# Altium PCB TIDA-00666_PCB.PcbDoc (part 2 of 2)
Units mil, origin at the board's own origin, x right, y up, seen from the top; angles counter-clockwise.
Board outline 1800 x 1650 mil, 4 copper layers (Layer 1 - Top Layer, Layer 2 - GND, Layer 3 - POWER, Layer 4 - Bottom Layer), stack 61.4 mil thick; 112 components, 67 nets, 298 pads, 149 vias.
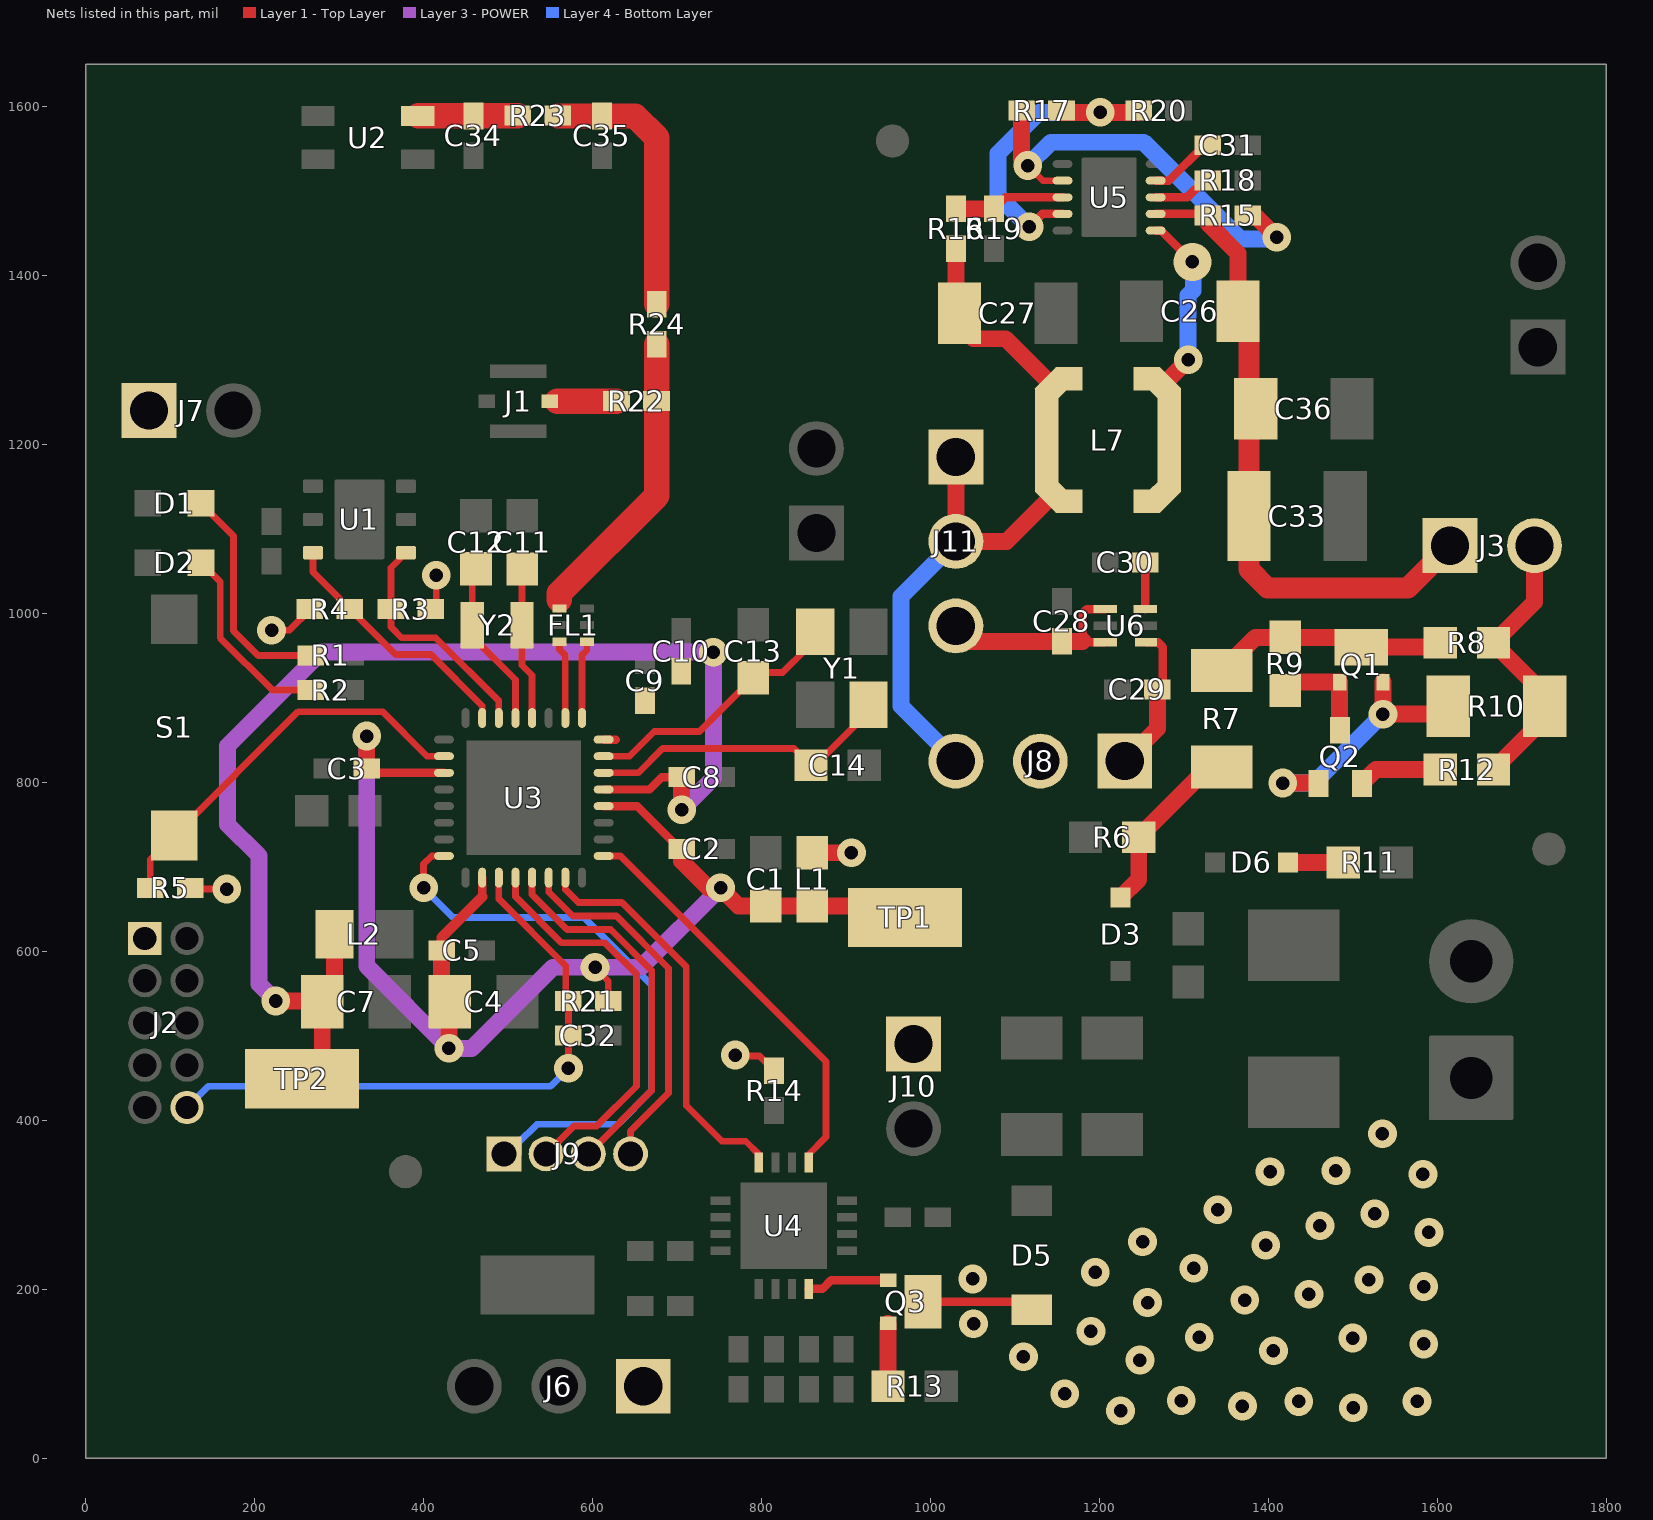
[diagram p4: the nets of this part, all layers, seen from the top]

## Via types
v1: diameter 34, hole 16, Layer 1 - Top Layer to Layer 4 - Bottom Layer, tented top, 127 vias
v2: diameter 19.68, hole 7.87, Layer 1 - Top Layer to Layer 4 - Bottom Layer, 20 vias
v3: diameter 45, hole 16, Layer 1 - Top Layer to Layer 4 - Bottom Layer, 2 vias

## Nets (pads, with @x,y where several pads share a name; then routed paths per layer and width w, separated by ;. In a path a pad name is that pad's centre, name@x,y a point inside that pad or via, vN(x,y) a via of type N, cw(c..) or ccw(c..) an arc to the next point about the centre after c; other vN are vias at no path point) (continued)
NetC30_1: C30.1 U6.3 | length 55.3
  Layer 1 - Top Layer w10: U6.3@1254.21,1005 C30.1@1254.21,1060.32
NetC31_1: C31.1 U5.4 | length 79.2
  Layer 1 - Top Layer w10: U5.4@1266.58,1512.09 1282.26,1512.09 1324.18,1554 C31.1@1328.38,1554
NetC34_1: C34.1 R23.2 U2.1 | length 117.9
  Layer 1 - Top Layer w30: U2.1@393.46,1589 R23.2@511.38,1589
NetC35_1: C35.1 R23.1 R24.1 | length 325
  Layer 1 - Top Layer w30: R23.1@559,1588.62 C35.1@611,1588.62 650.38,1588.62 676,1563 R24.1@676,1365.62
NetD1_2: D1.2 R1.1 | length 270.2
  Layer 1 - Top Layer w8: D1.2@136.5,1130 175,1091.5 175,979.17 204.17,950 R1.1@266.38,950
NetD2_2: D2.2 R2.2 | length 231.4
  Layer 1 - Top Layer w8: D2.2@136.5,1060 159.13,1037.37 159.13,970.87 221,909 R2.2@266.38,909
NetD3_1: D3.1 R6.1 R7.1 | length 213.4
  Layer 1 - Top Layer w20: D3.1@1225,663.31 1246.5,684.8 R6.1@1246.5,735 1329.41,817.91 R7.1@1345,817.91
NetD5_2: D5.2 Q3.3 | length 132.7
  Layer 1 - Top Layer w10: Q3.3@991.18,185 1110.53,185 D5.2@1120,175.53
  other v1: 1225,56 1500.33,59.63 1369.25,61.57 1436,67 1576,67 1297,68 1159,76 1248,116 1110,120 1406,127 1584,135 1500,142 1318,143 1190,150 1051,159 1257,184 1372,187 1448,194 1584,203 1519,211 1050,212 1195,220 1311.68,224.68 1397,252 1251,256 1590,267 1461,275 1526,289 1340,294 1583,336 1402,339 1480,340 1535,384
NetD6_2: D6.2 R11.2 | length 65.2
  Layer 1 - Top Layer w20: D6.2@1423.31,705 R11.2@1488.5,705
NetFL1_1: FL1.1 R22.1 R24.2 | length 349.4
  Layer 1 - Top Layer w30: 560.76,1016 560.76,1023.76 676,1139 R22.1@676,1250.62 ; R22.1@676,1251.38 R24.2@676,1318.38
NetJ1_1: J1.1 R22.2 | length 70.2
  Layer 1 - Top Layer w30: J1.1@558.13,1251 R22.2@628.38,1251
NetJ3_2: J3.2 R8.2 R10.1 R12.1 | length 335.3
  Layer 1 - Top Layer w20: R12.1@1666.5,815 1727.09,875.59 R10.1@1727.09,890 1727.09,904.41 R8.2@1666.5,965 1715,1013.5 J3.2@1715,1080
NetJ9_1: J9.1 U3.16 | length 712.7
  Layer 1 - Top Layer w8: v1(400,675) 400,703.05 409.59,712.64 U3.16@424.09,712.64
  Layer 4 - Bottom Layer w8: v1(400,675) 435,640 590,640 670,560 670,435 630,395 533.98,395 512.46,373.48 512.46,360 J9.1@495,360
NetJ9_2: J9.2 U3.20 | length 476.7
  Layer 1 - Top Layer w8: U3.20@508.74,687.05 508.74,664.54 563.41,609.87 614.96,609.87 652,572.83 652,440.07 604.88,392.95 577.95,392.95 J9.2@545,360
NetJ9_3: J9.3 U3.21 | length 447
  Layer 1 - Top Layer w8: U3.21@528.42,687.05 528.42,667.31 569.98,625.75 621.54,625.75 670,577.28 670,435 J9.3@595,360
NetJ9_4: J9.4 U3.22 | length 434.7
  Layer 1 - Top Layer w8: U3.22@548.11,687.05 548.11,670.07 576.56,641.62 628.11,641.62 690,579.73 690,431.93 645,386.93 J9.4@645,360
NetL7_1: L7.1 U5.1 | length 227.5
  Layer 1 - Top Layer w10: U5.1@1266.58,1453.03 1272.97,1453.03 v3(1310,1416) v3@1310,1410
  Layer 1 - Top Layer w20: L7.1@1274,1269 v1(1305,1300)
  Layer 4 - Bottom Layer w20: v1(1305,1300) 1305,1376 1311,1382 1311,1415 v3(1310,1416)
NetQ1_1: Q1.1 Q2.3 R9.1 | length 125.8
  Layer 1 - Top Layer w20: R9.1@1420,908.5 1430,918.5 Q1.1@1484.41,918.5 1484.41,862.09 Q2.3@1485,861.5
NetQ1_2: Q1.2 Q2.1 R10.2 | length 314.1
  Layer 1 - Top Layer w20: v1(1417,799) 1458.91,799 Q2.1@1459.41,798.5 ; Q1.2@1535.59,918.5 v1(1535.59,880.59) 1603.5,880.59 R10.2@1612.91,890
  Layer 4 - Bottom Layer w20: v1(1417,799) 1454,799 v1(1535.59,880.59)
NetQ1_3: Q1.3 R7.2 R8.1 R9.2 | length 281.8
  Layer 1 - Top Layer w20: R7.2@1345,932.09 1384.41,971.5 R9.2@1420,971.5 1498.35,971.5 Q1.3@1510,959.84 1598.35,959.84 R8.1@1603.5,965
NetQ2_2: Q2.2 R12.2 | length 99.7
  Layer 1 - Top Layer w20: Q2.2@1510.59,798.5 1527.09,815 R12.2@1603.5,815
NetQ3_1: Q3.1 U4.16 | length 98.3
  Layer 1 - Top Layer w10: U4.16@855.87,200.2 872.2,200.2 882.59,210.59 Q3.1@949.84,210.59
NetQ3_2: Q3.2 R13.2 | length 74.4
  Layer 1 - Top Layer w20: R13.2@949.84,85 Q3.2@949.84,159.41
NetR15_1: R15.1 R17.2 U5.7 | length 513.7
  Layer 1 - Top Layer w8: v1(1115,1530) 1132.91,1512.09 U5.7@1156.35,1512.09
  Layer 1 - Top Layer w20: R17.2@1107.84,1595 1107.84,1537.16 v1(1115,1530) ; R15.1@1375.62,1471 1384,1471 v1(1410,1445)
  Layer 4 - Bottom Layer w20: v1(1115,1530) 1142.52,1557.52 1252.48,1557.52 1367,1443 v1@1408,1443
NetR16_1: R16.1 R19.2 U5.8 | length 132.1
  Layer 1 - Top Layer w10: R19.2@1075,1478.62 1088.78,1492.4 U5.8@1156.35,1492.4
  Layer 1 - Top Layer w20: R16.1@1030,1478.62 R19.2@1075,1478.62
NetR17_1: R17.1 R20.2 U5.9 | length 386
  Layer 1 - Top Layer w10: v1(1116.96,1457.4) 1132.28,1472.72 U5.9@1156.35,1472.72
  Layer 1 - Top Layer w20: R17.1@1155.09,1595 1153.09,1593 v1(1201,1593) 1244.38,1593 R20.2@1246.38,1595
  Layer 4 - Bottom Layer w20: v1(1116.96,1457.4) 1080.13,1494.24 1080.13,1544.45 1128.68,1593 v1(1201,1593)
NetR18_2: R18.2 U5.3 | length 70
  Layer 1 - Top Layer w10: U5.3@1266.58,1492.4 1304.01,1492.4 1324.01,1512.4 R18.2@1328.34,1512.4
NRESET: C32.1 J2.10 R21.1 U3.19 | length 730.4
  Layer 1 - Top Layer w8: U3.19@489.05,687.05 489.05,661.78 568.13,582.71 568.13,543.25 571.38,540 C32.1@571.38,500 v1(571.38,461.38)
  Layer 4 - Bottom Layer w8: J2.10@120,415 145,440 550,440 v1(571.38,461.38)
RF_N: FL1.3 U3.2 | length 93.2
  Layer 1 - Top Layer w8: FL1.3@560.76,966.34 560.76,957.24 567.8,950.2 U3.2@567.8,876.02
RF_P: FL1.4 U3.1 | length 93.8
  Layer 1 - Top Layer w8: U3.1@587.48,876.02 587.48,950.48 593.24,956.24 FL1.4@593.24,966.34 ; FL1.4@594.24,966.34 FL1.4@595,965.58
SCL: R4.1 U1.6 U3.7 | length 303.4
  Layer 1 - Top Layer w8: U1.6@268.94,1071.65 268.94,1048.69 R4.1@312.62,1005 366.6,951.02 408.78,951.02 469.37,890.43 U3.7@469.37,876.02
SDA: R3.1 U1.1 U3.6 | length 279.4
  Layer 1 - Top Layer w8: U1.1@379.17,1071.65 361.38,1053.86 R3.1@361.38,1005 361.38,983.62 373.98,971.02 414.06,971.02 489.05,896.02 U3.6@489.05,876.02
SIMO: U3.25 U4.5 | length 492
  Layer 1 - Top Layer w8: U3.25@613.07,712.64 632.92,712.64 876.34,469.22 876.34,380 855.87,359.53 U4.5@855.87,349.8
SOMI: U3.23 U4.8 | length 478.9
  Layer 1 - Top Layer w8: U3.23@567.8,687.05 567.8,672.84 583.13,657.5 634.69,657.5 711,581.18 711,417 753,375 781.34,375 796.81,359.53 U4.8@796.81,349.8
USR_BTN: R5.1 S1.1 U3.10 | length 475.5
  Layer 1 - Top Layer w8: R5.1@76.38,675 76.38,708.43 S1.1@105,737.05 251.47,883.52 351.28,883.52 404.05,830.75 U3.10@424.09,830.75
VCC_SENSOR: J2.1 J6.1 J7.1 J8.2 J10.1 L1.2 R3.2 R4.2 R5.2 R14.1 | length 251.5
  Layer 1 - Top Layer w8: R5.2@123.62,675 124.62,676 127.11,673.51 v1(167,673.51) ; v1(220,980) 241.38,980 265.38,1004 R4.2@265.38,1005 ; R3.2@408.62,1005 415,1011.38 v1(415,1045) ; v1@761,476 797.62,476 R14.1@815,458.62
  Layer 1 - Top Layer w20: L1.2@860,716.5 v1(906.5,716.5)
  other v1: 769,477
VDDR: C7.1 C8.1 C9.1 C10.1 L2.2 TP2.1 U3.29 U3.32 | length 1542.2
  Layer 1 - Top Layer w10: U3.29@613.07,791.38 667.38,791.38 682.02,806.02 C8.1@705.43,806.02 ; U3.32@613.07,850.43 627.43,850.43
  Layer 1 - Top Layer w20: v1(225,541) C7.1@280,541 ; TP2.1@255.93,449.02 280,473.09 C7.1@280,540 294.57,554.57 L2.2@294.57,620 ; v1(705.43,767.4) C8.1@705.43,806.02
  Layer 3 - POWER w20: v1(225,541) 205,561 205,713 168,750 168,843 279,954 v1(743,954) 743,804.96 v1(705.43,767.4)
VDDS: C1.1 C2.1 C3.1 C4.1 C5.1 L1.1 R21.2 TP1.1 U3.11 U3.18 U3.28 | length 1635.1
  Layer 1 - Top Layer w8: v1(603,581) 603,580 618.62,564.38 R21.2@618.62,541 R21.2@618.62,540
  Layer 1 - Top Layer w10: C3.1@332.68,816.02 337.64,811.06 U3.11@424.09,811.06 ; 469.37,664.37 U3.18@469.37,687.05 ; U3.28@613.07,771.69 652.71,771.69 703.38,721.02 C2.1@705.43,721.02
  Layer 1 - Top Layer w12: C5.1@421.38,601 421.38,616.38 469.37,664.37
  Layer 1 - Top Layer w20: C3.1@332.68,816.02 v1(332.68,854.65) ; C5.1@421.38,601 421.38,548.62 430,540 v1(430,485) ; C2.1@705.43,721.02 705.43,706.57 737,675 v1(751.46,675) 772.95,653.5 C1.1@805,653.5 L1.1@860,653.5 956.5,653.5 TP1.1@970,640
  Layer 3 - POWER w20: v1(332.68,854.65) 332.68,582.32 v1(430,485) 457,485 553,581 v1(603,581) 657.46,581 v1(751.46,675)
VIN_DCDC: C26.1 C33.1 C36.1 J3.1 R15.2 U5.2 | length 769.5
  Layer 1 - Top Layer w10: U5.2@1266.58,1472.72 1326.66,1472.72 R15.2@1328.38,1471
  Layer 1 - Top Layer w20: R15.2@1328.38,1471 1328.38,1461.62 1364.05,1425.95 C26.1@1364.05,1357.4
  Layer 1 - Top Layer w25: C26.1@1364.05,1357.4 1376.91,1344.54 1376.91,1247 C33.1@1376.91,1115 1376.91,1052.09 1399,1030 1565,1030 J3.1@1615,1080
VIN_LDO: C28.1 J11.3 U6.4 U6.6 | length 243
  Layer 1 - Top Layer w10: U6.6@1206.97,965.63 1181.81,965.63 1180.31,967.13 1180.31,1000.35 1184.96,1005 U6.4@1206.97,1005
  Layer 1 - Top Layer w20: J11.3@1030,975 1038.31,966.69 C28.1@1155.59,966.69 1179.88,966.69 1180.31,967.13
VOUT_DCDC: C27.1 J8.3 J11.1 J11.2 L7.2 R16.2 | length 786.2
  Layer 1 - Top Layer w20: J11.1@1030,1185 J11.2@1030,1085 1090,1085 L7.2@1146,1141 ; R16.2@1030,1431.38 1030,1359.38 C27.1@1034.38,1355 1034.38,1341.33 1050.71,1325 1089,1325 L7.2@1145.5,1268.5
  Layer 4 - Bottom Layer w20: J8.3@1030,825 965,890 965,1020 J11.2@1030,1085
VOUT_LDO: C29.1 J8.1 U6.1 | length 176
  Layer 1 - Top Layer w10: U6.1@1255,965.63 1269.37,965.63 1275,960 1275,916.38 C29.1@1268.62,910
  Layer 1 - Top Layer w20: J8.1@1230,825 1268.62,863.62 C29.1@1268.62,910
X24M_N: C14.1 U3.30 Y1.1 | length 352.9
  Layer 1 - Top Layer w8: U3.30@613.07,811.06 654.09,811.06 683.03,840 838.5,840 C14.1@858.5,820 ; C14.1@861,817.5 916.5,872.99 Y1.1@916.5,881.69
X24M_P: C13.1 U3.31 Y1.3 | length 303.2
  Layer 1 - Top Layer w8: U3.31@613.07,830.75 643.78,830.75 673.03,860 726.5,860 C13.1@790,923.5 796.5,930 825,930 853.5,958.5 Y1.3@853.5,968.31
X32K_Q1: C11.2 U3.4 Y2.1 | length 181.6
  Layer 1 - Top Layer w8: C11.2@517,1052.5 516.53,1052.03 Y2.1@516.53,986 516.53,938.47 528.42,926.57 U3.4@528.42,876.02
X32K_Q2: C12.1 U3.5 Y2.2 | length 184.8
  Layer 1 - Top Layer w8: Y2.2@457.47,986 457.47,1047.94 C12.1@462.06,1052.53 ; Y2.2@458.47,971.53 508.74,921.26 U3.5@508.74,876.02
pads on no net: FID1.1 FID2.1 FID3.1 J2.6 J2.7 J2.8 SH-J1.0 SH-J2.0 SH-J3.0 SH-J4.0 SH-J5.0 SH-J6.0 U1.3 U1.4 U1.7 U3.3 U3.27 U4.11 U5.6 U6.5
copper on no net:
  other v2: 304.37,1073.62 343.74,1073.62 304.37,1111.02 343.74,1111.02 304.37,1148.43 343.74,1148.43

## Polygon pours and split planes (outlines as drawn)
GND on Layer 2 - GND "Layer 2 - GND-No Net" (solid, remove dead copper, pour order 9): 0,1650 1800,1650 1800,0 0,0
VCC_SENSOR on Layer 3 - POWER "Layer 3 - POWER-No Net" (solid, remove dead copper, pour order 10): 0,1650 1800,1650 1800,0 0,0
VIN_DCDC on Layer 1 - Top Layer "Layer 1 - Top Layer-No Net 1" (solid, remove dead copper, pour order 8): 1367.75,1441 1353.55,1441 1344,1450.55 1344,1476 1340,1480 1314.55,1480 1310,1475.45 1310,1345 1320,1335 1320,1216.85 1332.31,1204.54 1435,1204.54 1445,1214.54 1435,1204.54 1445,1214.54 1445,1363.76
GND on Layer 1 - Top Layer "Layer 1 - Top Layer-No Net" (solid, remove dead copper, pour order 11): 0,0 0,1650 1800,1650 1800,0
VOUT_DCDC on Layer 1 - Top Layer "Layer 1 - Top Layer-No Net 2" (solid, remove dead copper, pour order 7): 1150,1125 1130,1105 1090,1065 990,1065 970,1085 960,1095 960,1400 960,1420 990,1450 1045,1450 1055,1450 1096.5,1408.5 1096.5,1333.5 1150,1280
NetD5_2 on Layer 1 - Top Layer "Layer 1 - Top Layer-No Net 3" (solid, remove dead copper, pour order 4): 965,220 995,250 1065,250 1155,250 1200,295 1275,295 1410,430 1630,430 1630,15 1165,15 1050,130 985,130 965,150
LOOP_P on Layer 1 - Top Layer "Layer 1 - Top Layer-No Net 4" (solid, remove dead copper, pour order 6): 1055,265 1060,260 1149.01,260 1195.32,306.3 1196.25,307.24 1275,307.24 1277.24,307.24 1320,350 1320,400 1320,430 1305,445 1165,445 1065,445 1055,435
LOOP_M on Layer 1 - Top Layer "Layer 1 - Top Layer-No Net 5" (solid, remove dead copper, pour order 5): 1130,450 1065,450 1055,460 1055,545 1055,560 1090,595 1236.27,595 1318.46,512.81 1320,511.27 1320,480 1320,455 1315,450
VDDR on Layer 1 - Top Layer "Layer 1 - Top Layer-No Net 6" (solid, remove dead copper, pour order 3): 765,940 765,915 720,870 665,870 640,845 605,845 602,848 602,872 645,915 685,915 690,920 690,950 695,955 715,955 730,970 735,975 750,975 755,975 765,965
VDDS on Layer 1 - Top Layer "Layer 1 - Top Layer-No Net 7" (solid, remove dead copper, pour order 2): 870,684 1037,684 1048,673 1048,608 1040,600 795,600 635,760 635,765 633,767 633,776 656,776 697,735 720,735 730,725 730,720 730,708.9 738.06,700.84 765.57,700.84 776.79,689.63 782.41,684
GND on Layer 4 - Bottom Layer "Layer 4 - Bottom Layer-No Net" (solid, remove dead copper, pour order 14): 0,1650 1800,1650 1800,0 0,0
NetD5_2 on Layer 4 - Bottom Layer "Layer 4 - Top Layer-No Net 3" (solid, remove dead copper, pour order 0): 965,220 995,250 1065,250 1155,250 1200,295 1275,295 1410,430 1630,430 1630,15 1165,15 1050,130 985,130 965,150

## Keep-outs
Keep-Out Layer:
  text ".Layer_Name" at 577,-858.49 h60

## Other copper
Layer 1 - Top Layer:
  pour cut-out: 412.48,1649.91 255,1649.91 255,1360 412.48,1360
  pour cut-out: 1160,1307.6 1276.32,1308.18 1309.32,1275.18 1309.32,1135.18 1279.13,1105 1160,1105 1149.57,1115.43 1149.57,1290
  pour cut-out: 440,860 595,860 595,705 440,705
  pour cut-out: 1170,1535 1170,1465 1195,1465 1210,1450 1250,1450 1250,1512.35 1227.35,1535
  pour cut-out: 185,1090 185,990 270,990 270,1090
  pour cut-out: 1534.4,920 1534.4,770 1265,770 1265,920
  pour cut-out: 650,402.13 650,282.17 675,257.17 675,230 670,225 605,225 605,190 675,190 745,120 745,70 761,54 930,54 930,202.23 992.26,264.49 992.26,422.61 980,434.86 925.14,434.86 910,450 697.87,450
  text ".Layer_Name" at 577,-858.49 h60
Layer 3 - POWER:
  pour cut-out: 412.48,1650.53 255,1650.53 255,1360 412.48,1360
  text ".Layer_Name" at 577,-858.49 h60
Layer 2 - GND:
  pour cut-out: 412.48,1649.91 255,1649.91 255,1360 412.48,1360
  text ".Layer_Name" at 577,-858.49 h60
Layer 4 - Bottom Layer:
  pour cut-out: 412.48,1649.91 255,1649.91 255,1360 412.48,1360
  text ".Layer_Name" at 577,-858.49 h60

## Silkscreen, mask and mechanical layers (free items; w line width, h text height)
Top Overlay:
  text ".Layer_Name" at 577,-858.49 h60
Bottom Overlay:
  region: 1519,917 1519,1217 1419,1217 1419,917
  text "'.PRJ_Number'.PCB_Rev-" at 1325,715 h108.27 r270
  text ".Layer_Name" at 577,-858.49 h60
Top Paste:
  text ".Layer_Name" at 577,-858.49 h60
Bottom Paste:
  text ".Layer_Name" at 577,-858.49 h60
Top Solder:
  text ".Layer_Name" at 577,-858.49 h60
  text ".Layer_Name" at 577,-858.49 h60
Bottom Solder:
  text ".Layer_Name" at 577,-858.49 h60
Drill Guide:
  text ".Layer_Name" at 577,-858.49 h60
M1 Board Outline:
  the board outline again, w10
  text ".Layer_Name" at 577,-858.49 h60
M2 Board Dimensions:
  rectangle: 0,-275 125,-150
  rectangle: 125,-400 500,-275
  lines w7: 0,-275 1000,-275 ; 125,-400 125,-150 ; 250,-400 250,-150 ; 500,-400 500,-150 ; 750,-400 750,-150 ; 0,-400 1000,-400 1000,-150 0,-150 0,-400
  text ".Layer_Name" at 577,-858.49 h60
M3 3D STEP Top:
  text ".Layer_Name" at 577,-858.49 h60
M4 3D STEP Bottom:
  text ".Layer_Name" at 577,-858.49 h60
M5 Assembly Top:
  lines w10: -292,-930.17 6308,-930.17 ; -292,-726.83 6310,-726.83 ; -292,-523.5 -292,-1133.5 3713,-1133.5 6310,-1133.5 6310,-523.5 -291.5,-523.5 -291.5,-1133.5 1284,-1133.5 ; 2173,-1133.5 2173,-523.5 ; 3440,-726.83 3440,-523.5 ; 4280,-726.83 4280,-523.5 ; 4902,-1140 4902,-937.17
  text "COMPONENTS MARKED 'DNP' SHOULD NOT BE POPULATED." at 1153.5,-318.5 h60
  text "ASSEMBLY VARIANT:" at 1153,-434 h60
  text ".VariantName" at 2189,-434 h60
  text "PCB VIEWED FROM TOP SIDE" at -228.5,-655.67 h60
  text "BOARD #:" at 2248,-655.67 h60
  text ".PRJ_Number" at 2793.5,-655.67 h60
  text "REV:" at 3638,-655.67 h60
  text ".PCB_Rev" at 3929.5,-655.67 h60
  text "SVN REV:" at 4476,-655.67 h60
  text ".VersionControl_RevNumber" at 4982,-655.67 h60
  text "TID #:" at 2248,-859 h60
  text ".TID" at 2793.5,-859 h60
  text "PLOT NAME =" at -228.5,-1064.34 h60
  text ".plot_File_Name" at 577,-1064.34 h60
  text "GENERATED    :" at 2250,-1064.34 h60
  text ".Print_Date" at 3119.5,-1064.34 h60
  text ".Print_Time" at 3848.5,-1064.34 h60
  text "TEXAS INSTRUMENTS" at 5113,-1064.34 h60
M6 Assembly Bottom:
  lines w10: -292.5,-727.33 6309.5,-727.33 ; -290.5,-930.67 6309.5,-930.67 ; 1115.5,-1140.5 1115.5,-937.67 ; 1737.5,-727.33 1737.5,-524 ; 2577.5,-727.33 2577.5,-524 ; 3844.5,-1134 3844.5,-524 ; 4733.5,-1134 6309,-1134 6309,-524 -292.5,-524 -292.5,-1134 2304.5,-1134 6309.5,-1134 6309.5,-524
  text "COMPONENTS MARKED 'DNP' SHOULD NOT BE POPULATED." at 6102,-318 h60
  text ".VariantName" at 5058,-434 h60
  text "ASSEMBLY VARIANT:" at 6097,-434 h60
  text ".VersionControl_RevNumber" at 1035.5,-656.17 h60
  text "SVN REV:" at 1541.5,-656.17 h60
  text ".PCB_Rev" at 2088,-656.17 h60
  text "REV:" at 2379.5,-656.17 h60
  text ".PRJ_Number" at 3224,-656.17 h60
  text "BOARD #:" at 3769.5,-656.17 h60
  text "PCB VIEWED FROM BOTTOM SIDE" at 6246,-656.17 h60
  text ".TID" at 3224,-859.5 h60
  text "TID #:" at 3769.5,-859.5 h60
  text "TEXAS INSTRUMENTS" at 904.5,-1064.84 h60
  text ".Print_Time" at 2169,-1064.84 h60
  text ".Print_Date" at 2898,-1064.84 h60
  text "GENERATED    :" at 3767.5,-1064.84 h60
  text ".plot_File_Name" at 5440.5,-1064.84 h60
  text "PLOT NAME =" at 6246,-1064.84 h60
M9 Title Sheet:
  drawing of 57 lines, arcs and shapes, not listed
  text "1" at 739.84,8036.5 h70
  text "2" at 3235.5,8036.5 h70
  text "3" at 5724.84,8036.5 h70
  text "4" at 8231.51,8036.5 h70
  text "5" at 10730.5,8036.5 h70
  text "6" at 13235.5,8036.5 h70
  text "A" at -416.5,6893.5 h70
  text "A" at 14383.5,6893.5 h70
  text "B" at -416.5,4513.5 h70
  text "B" at 14383.5,4513.5 h70
  text "C" at -416.5,2138.5 h70
  text "C" at 14383.5,2138.5 h70
  text "PROJECT TITLE:" at 11343.5,277.5 h45
  text ".PRJ_Title" at 11393.5,144.17 h70
  text "DESIGNED FOR:" at 11343.5,-23.5 h45
  text ".PRJ_Customer" at 11393.5,-163.5 h70
  text "D" at -416.5,-231.5 h70
  text "D" at 14383.5,-231.5 h70
  text "FILE NAME:" at 11343.5,-323.5 h45
  text ".PCB_File_Name_No_Path" at 11393.5,-443.5 h70
  text "Texas Instruments (TI) and/or its licensors do not warrant the accuracy or completeness of this specification" at 6374,-605.34 h45
  text "ENGINEER:" at 11343.5,-613.5 h45
  text "LAYOUT BY:" at 12848.5,-613.5 h45
  text "or any information contained therein. TI and/or its licensors do not warrant that this design will meet" at 6329.01,-718 h45
  text ".PRJ_Engineer" at 11393.5,-768.49 h70
  text ".PCB_Layout" at 12899,-768.49 h70
  text "the specifications, will be suitable for your application or fit for any particular purpose, or will operate in" at 6329.01,-830.67 h45
  text ".Layer_Name" at 577,-858.49 h60
  text "ALTIUM DESIGNER VERSION:" at 12848.5,-923.5 h45
  text "an implementation. TI and/or its licensors do not warrant that the design is production worthy. You should" at 6329.01,-943.33 h45
  text "completely validate and test your design implementation to confirm the system functionality for your application." at 6374,-1056 h45
  text ".print_Scale" at 11393.5,-1056.83 h70
  text ".Application_BuildNumber" at 12899,-1056.83 h70
  text "1" at 739.84,-1263.5 h70
  text "2" at 3235.5,-1263.5 h70
  text "3" at 5724.84,-1263.5 h70
  text "4" at 8231.51,-1263.5 h70
  text "5" at 10730.5,-1263.5 h70
  text "6" at 13235.5,-1263.5 h70
M10 Fab Notes:
  drawing of 173 lines, arcs and shapes, not listed
  text "DESIGN INFORMATION" at 12378.02,6201 h60
  text "MIN. TRACK WIDTH:" at 11733.46,6021 h60
  text "8" at 12829.7,6021 h60
  text "MIL" at 12984.46,6021 h60
  text "MIN. CLEARANCE:" at 11733.46,5889 h60
  text "0.2" at 12769.7,5889 h60
  text "mm" at 12984.46,5889 h60
  text "MIN. VIA PAD SIZE:" at 11733.46,5757 h60
  text "24" at 12799.71,5757 h60
  text "MIL" at 12984.46,5757 h60
  text "0.05mm (2MIL)" at 12428.46,5615.29 h60
  text "MINIMUM ANNULAR RING" at 11404.23,5611 h60
  text "EXTERNAL" at 13136.46,5611 h60
  text "PER" at 11604.23,5493 h60
  text "IPC-D-275 CLASS 2 LEVEL C" at 11824.23,5493 h60
  text "MIL, HOLES" at 13312.46,5380.71 h60
  text "+/-" at 12920,5380 h60
  text "+/-" at 13774,5380 h60
  text "REGISTRATION TOLERANCES:" at 11404.23,5375 h60
  text "METAL" at 12604,5375 h60
  text "5" at 13180.2,5375 h60
  text "3" at 14013.2,5375 h60
  text "MIL" at 14129.46,5375 h60
  text "+/-" at 13774,5262 h60
  text "HOLE SIZE TOLERANCE (UNLESS OTHERWISE SPECIFIED):" at 11404.23,5257 h60
  text "3" at 14013.2,5257 h60
  text "MIL" at 14129.46,5257 h60
  text "MATERIAL:" at 11329.46,5047.54 h60
  text "FR-4 High Tg" at 12315.9,4907.21 h60
  text "FR-408" at 11750.46,4898.64 h60
  text "OTHER" at 13238.46,4898.64 h60
  text "X" at 12161,4895 h60
  text "62 MIL (1.6mm) +/-10%" at 12070.56,4735.92 h60
  text "THICKNESS:" at 11404.23,4731.64 h60
  text "X" at 11942.4,4731.64 h60
  text "OTHER" at 13355.46,4731.64 h60
  text "TOLERANCE:" at 11404.23,4573.64 h60
  text "X" at 12243.53,4573.64 h60
  text "ANSI IPC-6012 TYPE 3 CLASS 2" at 12430.48,4573.64 h60
  text "OTHER +/-" at 12430.46,4417.64 h60
  text "BOW & TWIST:" at 11404.23,4260.64 h60
  text "X" at 12243.53,4260.64 h60
  text "ANSI IPC-6012 TYPE 3 CLASS 2" at 12430.48,4260.64 h60
  text "OTHER +/-" at 12430.46,4102.13 h60
  text "DRILLING:" at 11329.46,3963.64 h60
  text "REFERENCE:" at 11404.23,3846.64 h60
  text "X" at 12052.46,3846.64 h60
  text "AS SHOWN" at 12239.46,3846.64 h60
  text "X" at 12953.46,3846.64 h60
  text "NC_DRILL FILES" at 13090.46,3846.64 h60
  text "PTH COPPER THICKNESS:" at 11404.23,3688.64 h60
  text "X" at 12534.46,3688.64 h60
  text "20-30 um" at 12671.46,3688.64 h60
  text "OTHER" at 13388.46,3688.64 h60
  text "BOARD FINISH:" at 11329.46,3529.64 h60
  text "SILKSCREEN:" at 11484.68,3411.64 h60
  text "X" at 12433.46,3411.64 h60
  text "TOP" at 12559.46,3411.64 h60
  text "X" at 12943.46,3411.64 h60
  text "BOTTOM" at 13070.46,3411.64 h60
  text "SILKSCREEN COLOR:" at 11484.68,3244.64 h60
  text "X" at 12432.42,3244.64 h60
  text "WHITE" at 12559.46,3244.64 h60
  text "OTHER" at 13070.46,3244.64 h60
  text "X" at 12563.42,3085.44 h60
  text "GREEN" at 12690.46,3085.44 h60
  text "OTHER" at 13308.46,3085.44 h60
  text "SOLDER RESIST COLOR:" at 11484.68,3074.64 h60
  text "X" at 12563.42,2915.44 h60
  text "MATTE" at 12690.46,2915.44 h60
  text "SEMI-GLOSS" at 13308,2914.8 h60
  text "IMMERSION GOLD (ENIG)" at 12390.46,2726.92 h60
  text "ENEPIG" at 13728,2723.64 h60
  text "SURFACE FINISH:" at 11329.46,2722.64 h60
  text "X" at 12203.51,2722.64 h60
  text "IMM. TIN/SILVER OR EQUIV" at 11659,2565.64 h60
  text "OTHER" at 13090.46,2565.64 h60
  text "ARRAY/PANEL:" at 11329.46,2386.64 h60
  text "CUT AND TRIM PER M1 BOARD OUTLINE" at 12390.46,2382.35 h60
  text "N.C. ROUTE" at 12390.46,2230.64 h60
  text "X" at 13069.46,2230.64 h60
  text "V. SCORE" at 13256.46,2230.64 h60
  text "CERTIFICATION:" at 11329.46,2093.64 h60
  text "MATERIALS AND WORKMANSHIP FOR ALL PCBS" at 12054.46,2093.64 h60
  text "TO MEET OR EXCEED THE REQUIREMENTS OF:" at 12054.46,1995.64 h60
  text "X" at 11680.96,1859.13 h60
  text "ANSI IPC-A-600F CLASS ->" at 11819.96,1859.13 h60
  text "X" at 13459.02,1859.13 h60
  text "2" at 13577.96,1859.14 h60
  text "1" at 13262.96,1857.64 h60
  text "3" at 13931.96,1857.64 h60
  text "X" at 12495.02,1699.64 h60
  text "RoHS" at 12631.96,1699.64 h60
  text "OTHER" at 13276.36,1699.64 h60
  text "PER ORDER" at 13673.42,1699.64 h60
  text "ALL BOARDS MUST MEET OR EXCEED UL94-V0 REQUIREMENTS." at 11357,1534 h60
  text "PCB MUST BEAR THE UL94V-0 UL REGISTERED MATERIAL ID NUMBER" at 11357,1414 h60
  text "ADDITIONAL REQUIREMENTS:" at 11329.46,1240.64 h60
  text "MICROSECTION:" at 11404.23,1125.64 h60
  text "YES" at 12309.96,1125.64 h60
  text "REQUIRED" at 13171.46,969.49 h60
  text "BARE BOARD ELEC. TEST:" at 11404.23,966.64 h60
  text "NONE" at 12709.96,966.64 h60
  text "X" at 13044.46,966.64 h60
  text "PER ORDER" at 13763.46,966.64 h60
  text ".Layer_Name" at 577,-858.49 h60
M11 Gerber Information:
  lines w10: -292,-930.17 6308,-930.17 ; -292,-726.83 6310,-726.83 ; -292,-523.5 -292,-1133.5 3713,-1133.5 6310,-1133.5 6310,-523.5 -291.5,-523.5 -291.5,-1133.5 1284,-1133.5 ; 2173,-1133.5 2173,-523.5 ; 3440,-726.83 3440,-523.5 ; 4280,-726.83 4280,-523.5 ; 4902,-1140 4902,-937.17
  text "ALL ARTWORK VIEWED FROM TOP SIDE" at -228.5,-655.67 h60
  text "BOARD #:" at 2248,-655.67 h60
  text ".PRJ_Number" at 2793.5,-655.67 h60
  text "REV:" at 3638,-655.67 h60
  text ".PCB_Rev" at 3929.5,-655.67 h60
  text "SVN REV:" at 4476,-655.67 h60
  text ".VersionControl_RevNumber" at 4982,-655.67 h60
  text "LAYER NAME =" at -228.5,-858.49 h60
  text "TID #:" at 2248,-859 h60
  text ".TID" at 2793.5,-859 h60
  text "PLOT NAME =" at -228.5,-1064.34 h60
  text ".plot_File_Name" at 577,-1064.34 h60
  text "GENERATED    :" at 2250,-1064.34 h60
  text ".Print_Date" at 3119.5,-1064.34 h60
  text ".Print_Time" at 3848.5,-1064.34 h60
  text "TEXAS INSTRUMENTS" at 5113,-1064.34 h60
M12 Stackup:
  drawing of 295 lines, arcs and shapes, not listed
  text "Layer" at 9291.09,7753 h60
  text "Name" at 9701,7753 h60
  text "Material" at 11110.59,7753 h60
  text "Thickness" at 11970.36,7753 h60
  text "Constant" at 12620.19,7753 h60
  text "Board Layer Stack" at 13190.05,7753 h60
  text "1" at 9291.09,7633 h60
  text "Top Overlay" at 9701,7633 h60
  text "2" at 9291.09,7513 h60
  text "Top Solder" at 9701,7513 h60
  text "Solder Resist" at 11110.59,7513 h60
  text "0.40mil" at 11970.36,7513 h60
  text "3.5" at 12620.19,7513 h60
  text "3" at 9291.09,7393 h60
  text "Layer 1 - Top Layer" at 9701,7393 h60
  text "Copper" at 11110.59,7393 h60
  text "1.40mil" at 11970.36,7393 h60
  text "4" at 9291.09,7273 h60
  text "Dielectric1" at 9701,7273 h60
  text "370HR" at 11110.59,7273 h60
  text "18.60mil" at 11970.36,7273 h60
  text "4.2" at 12620.19,7273 h60
  text "5" at 9291.09,7153 h60
  text "Layer 2 - GND" at 9701,7153 h60
  text "Copper" at 11110.59,7153 h60
  text "1.40mil" at 11970.36,7153 h60
  text "6" at 9291.09,7033 h60
  text "Dielectric3" at 9701,7033 h60
  text "370HR" at 11110.59,7033 h60
  text "18.60mil" at 11970.36,7033 h60
  text "4.2" at 12620.19,7033 h60
  text "7" at 9291.09,6913 h60
  text "Layer 3 - POWER" at 9701,6913 h60
  text "Copper" at 11110.59,6913 h60
  text "1.40mil" at 11970.36,6913 h60
  text "8" at 9291.09,6793 h60
  text "Dielectric2" at 9701,6793 h60
  text "370HR" at 11110.59,6793 h60
  text "18.60mil" at 11970.36,6793 h60
  text "4.2" at 12620.19,6793 h60
  text "9" at 9291.09,6673 h60
  text "Layer 4 - Bottom Layer" at 9701,6673 h60
  text "Copper" at 11110.59,6673 h60
  text "1.40mil" at 11970.36,6673 h60
  text "10" at 9291.09,6553 h60
  text "Bottom Solder" at 9701,6553 h60
  text "Solder Resist" at 11110.59,6553 h60
  text "0.40mil" at 11970.36,6553 h60
  text "3.5" at 12620.19,6553 h60
  text "11" at 9291.09,6433 h60
  text "Bottom Overlay" at 9701,6433 h60
  text ".Layer_Name" at 577,-858.49 h60
M13 Component Bodies Top:
  text ".Layer_Name" at 577,-858.49 h60
M14 Component Bodies Bottom:
  text ".Layer_Name" at 577,-858.49 h60
M15 Courtyards Top:
  text ".Layer_Name" at 577,-858.49 h60
M16 Courtyards Bottom:
  text ".Layer_Name" at 577,-858.49 h60
Drill Drawing:
  lines w10: 3893.16,2139.68 3906.99,2139.68 3920.82,2125.85 3934.66,2139.68 3948.49,2139.68 3934.66,2153.52 3948.49,2167.35 3934.66,2167.35 3920.82,2181.18 3906.99,2167.35 3893.16,2167.35 3906.99,2153.52 3893.16,2139.68 ; 3893.16,2250.35 3948.49,2250.35 3948.49,2305.68 3893.16,2305.68 3893.16,2250.35 ; 3893.16,2374.85 3893.16,2388.68 3906.99,2402.52 3893.16,2416.35 3893.16,2430.18 3906.99,2430.18 3920.82,2416.35 3934.66,2430.18 3948.49,2430.18 3948.49,2416.35 3934.66,2402.52 3948.49,2388.68 3948.49,2374.85 3934.66,2374.85 3920.82,2388.68 3906.99,2374.85 3893.16,2374.85 ; 3893.16,2554.68 3948.49,2554.68 3920.82,2499.35 3893.16,2554.68 ; 3893.16,2637.68 3906.99,2637.68 3906.99,2623.85 3934.66,2623.85 3934.66,2637.68 3948.49,2637.68 3948.49,2665.35 3934.66,2665.35 3934.66,2679.18 3906.99,2679.18 3906.99,2665.35 3893.16,2665.35 3893.16,2637.68 ; 3893.16,2748.35 3920.82,2762.18 3948.49,2748.35 3934.66,2776.02 3948.49,2803.68 3920.82,2789.85 3893.16,2803.68 3906.99,2776.02 3893.16,2748.35
  lines w12: 3843,2088.5 7389.49,2088.5 ; 3843,2835.5 7389.49,2835.5 ; 4181.01,1964 4181.01,2960 ; 4513.17,1964 4513.17,2960 ; 5149.65,1964 5149.65,2960 ; 5408.85,1964 5408.85,2960 ; 5784.09,1964 5784.09,2960 ; 6977.14,1964 6977.14,2960 ; 3843,1964 7389.49,1964 7389.49,2960 3843,2960 3843,1964
  text "Symbol" at 3917.7,2872.85 h72
  text "Quantity" at 4218.36,2872.85 h72
  text "Finished Hole Size" at 4550.52,2872.85 h72
  text "Plated" at 5187,2872.85 h72
  text "Hole Type" at 5446.2,2872.85 h72
  text "Drill Layer Pair" at 5821.44,2872.85 h72
  text "Tolerance" at 7014.49,2872.85 h72
  text "20" at 4218.36,2748.35 h60
  text "7.87mil (0.200mm)" at 4550.52,2748.35 h60
  text "PTH" at 5187,2748.35 h60
  text "Round" at 5446.2,2748.35 h60
  text "Layer 1 - Top Layer - Layer 4 - Bottom Layer" at 5821.44,2748.35 h60
  text "129" at 4218.36,2623.85 h60
  text "16.00mil (0.406mm)" at 4550.52,2623.85 h60
  text "PTH" at 5187,2623.85 h60
  text "Round" at 5446.2,2623.85 h60
  text "Layer 1 - Top Layer - Layer 4 - Bottom Layer" at 5821.44,2623.85 h60
  text "10" at 4218.36,2499.35 h60
  text "27.56mil (0.700mm)" at 4550.52,2499.35 h60
  text "PTH" at 5187,2499.35 h60
  text "Round" at 5446.2,2499.35 h60
  text "Layer 1 - Top Layer - Layer 4 - Bottom Layer" at 5821.44,2499.35 h60
  text "4" at 4218.36,2374.85 h60
  text "29.53mil (0.750mm)" at 4550.52,2374.85 h60
  text "PTH" at 5187,2374.85 h60
  text "Round" at 5446.2,2374.85 h60
  text "Layer 1 - Top Layer - Layer 4 - Bottom Layer" at 5821.44,2374.85 h60
  text "19" at 4218.36,2250.35 h60
  text "45.28mil (1.150mm)" at 4550.52,2250.35 h60
  text "PTH" at 5187,2250.35 h60
  text "Round" at 5446.2,2250.35 h60
  text "Layer 1 - Top Layer - Layer 4 - Bottom Layer" at 5821.44,2250.35 h60
  text "2" at 4218.36,2125.85 h60
  text "50.00mil (1.270mm)" at 4550.52,2125.85 h60
  text "PTH" at 5187,2125.85 h60
  text "Round" at 5446.2,2125.85 h60
  text "Layer 1 - Top Layer - Layer 4 - Bottom Layer" at 5821.44,2125.85 h60
  text "184 Total" at 4218.36,2001.35 h60
  text ".Layer_Name" at 577,-858.49 h60
M17 Embedded Cavity:
  text ".Layer_Name" at 577,-858.49 h60
M18 Embedded Assembly:
  text ".Layer_Name" at 577,-858.49 h60
M19 Embedded Keepout:
  text ".Layer_Name" at 577,-858.49 h60

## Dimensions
0,-400 to 1000,-400 on M2 Board Dimensions
0,0 to 1800,0 on M2 Board Dimensions
0,0 to 0,1650 on M2 Board Dimensions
